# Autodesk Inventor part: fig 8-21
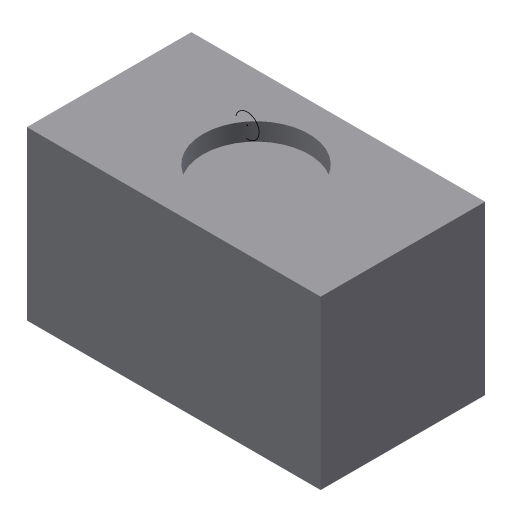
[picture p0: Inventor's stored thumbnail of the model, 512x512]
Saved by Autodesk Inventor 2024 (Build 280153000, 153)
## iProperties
Created: 2011-07
Part Number: fig 8-21
Material: Generic
Document SubType Name: Modeling
Designer: CadCim
Density: 1 g/cm^3
Appearance: Default
Author: CadCim
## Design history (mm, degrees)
sketch "Sketch1"
  geometry: L1 (-18, 10)-(7, 10); L2 (7, 10)-(7, -4); L3 (7, -4)-(-18, -4); L4 (-18, -4)-(-18, 10); 1 further point
  constraints: 8 end point, 2 parallel, 1 horizontal, 1 perpendicular
extrude "Extrusion1" new body sketch "Sketch1" distance "d0" = 14.25; taper "d1" = 0 deg
sketch "Sketch2"
  geometry: C1 r 4.5 at (-5.5, 3); 1 further point
  constraints: 1 centre point
extrude "Extrusion2" cut sketch "Sketch2" distance "d2" = 1.5; taper "d3" = 0 deg
workplane "Work Plane2"
sketch "Sketch4"
  geometry: C1 r 1 at (9, -14); 1 further point
  constraints: 1 centre point
body "Solid1"
other parameters: "d4" = -4.25
